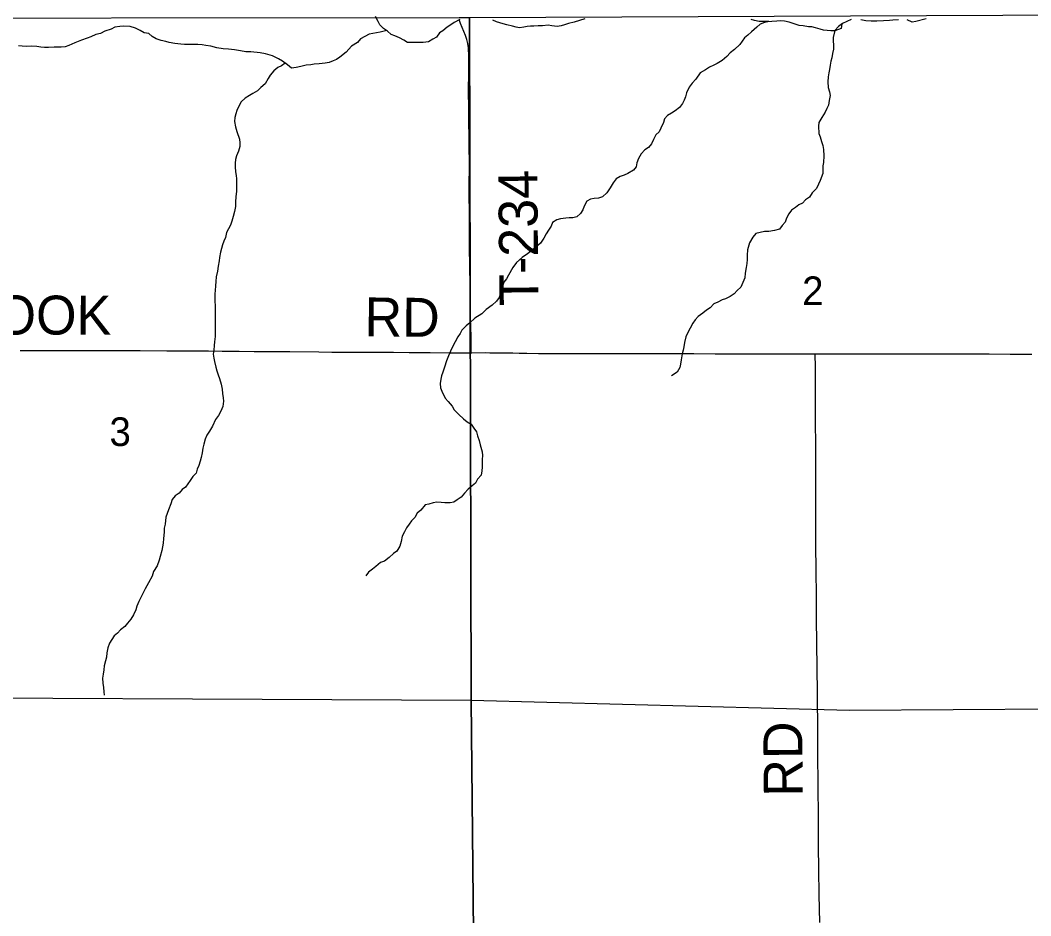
# Model space of a CAD drawing. Extents: x 0 to 34, y 0 to 22.
# Drawn here: x 2.961 to 4.435, y 14.561 to 15.868 of the extents above; entities that cross this region are included whole.
import ezdxf

# ---------------------------------------------------------------- set-up
doc = ezdxf.new("R2010")
doc.units = 0
for name, color, linetype in [('Default', 7, 'Continuous'), ('GM_X_County_Road', 7, 'Continuous'), ('GM_X_County_Road_Text', 7, 'Continuous'), ('GM_X_Minor_River', 7, 'Continuous'), ('GM_X_Section', 7, 'Continuous'), ('GM_X_Section_Text', 7, 'Continuous'), ('GM_X_Township_Road', 7, 'Continuous'), ('GM_X_Township_Road_Text', 7, 'Continuous')]:
    doc.layers.add(name, color=color, linetype=linetype)

msp = doc.modelspace()

# ---------------------------------------------------------------- linework, layer by layer
at = {"layer": 'Default'}
for points in [[(2.605, 14.1), (3.6266, 14.1), (3.6188, 14.8751), (2.6012, 14.88)], [(3.6266, 14.1), (4.6336, 14.1), (4.6247, 14.8633), (4.1707, 14.8603), (3.6188, 14.8751)]]:
    msp.add_lwpolyline(points, close=True, dxfattribs=at)
at = {"layer": 'GM_X_County_Road'}
for points in [[(2.9606, 15.3862), (2.9917, 15.3861), (3.0134, 15.3862), (3.0476, 15.3862), (3.0724, 15.3862), (3.1035, 15.3859), (3.1181, 15.386), (3.1359, 15.386), (3.1749, 15.3858), (3.1935, 15.3857), (3.2176, 15.3856), (3.2355, 15.3854), (3.2556, 15.3851), (3.268, 15.385), (3.2804, 15.3849), (3.3023, 15.3847), (3.3268, 15.3845), (3.3415, 15.3844), (3.3541, 15.3845), (3.3966, 15.3841), (3.4156, 15.3838), (3.4396, 15.3837), (3.4683, 15.3837), (3.4837, 15.3835), (3.5055, 15.3835), (3.5281, 15.3834), (3.559, 15.3831), (3.5869, 15.3826), (3.5962, 15.3828), (3.6077, 15.3826), (3.6186, 15.3827)], [(3.6186, 15.3827), (3.6197, 15.3828), (3.6397, 15.383), (3.6461, 15.3829), (3.6578, 15.3829), (3.6706, 15.3828), (3.6798, 15.3827), (3.6891, 15.3822), (3.6999, 15.3822), (3.717, 15.3819), (3.7418, 15.3818), (3.7574, 15.3818), (3.7729, 15.3819), (3.804, 15.3819), (3.8475, 15.3819), (3.8847, 15.3819), (3.9065, 15.3818), (3.9251, 15.3816), (3.9437, 15.3815), (3.9748, 15.3813), (4.009, 15.3813), (4.0338, 15.3813), (4.071, 15.3811), (4.0866, 15.3812), (4.1076, 15.3812), (4.1209, 15.3812)], [(4.1209, 15.3812), (4.151, 15.3814), (4.1728, 15.3812), (4.1976, 15.381), (4.2219, 15.3811), (4.2536, 15.3811), (4.3095, 15.3813), (4.3405, 15.3812), (4.3747, 15.3811), (4.4053, 15.3809), (4.4244, 15.3807), (4.4368, 15.3809)], [(4.1275, 14.551), (4.1269, 14.5913), (4.1262, 14.6284), (4.1258, 14.6626), (4.1255, 14.7029), (4.1251, 14.7526), (4.1247, 14.7961), (4.1246, 14.8272), (4.124, 14.8862), (4.123, 14.9949), (4.1228, 15.0291), (4.1225, 15.0632), (4.122, 15.1036), (4.122, 15.1253), (4.1217, 15.178), (4.1216, 15.2028), (4.1218, 15.2432), (4.1214, 15.2867), (4.1212, 15.3364), (4.1212, 15.3612), (4.1209, 15.3812)]]:
    msp.add_lwpolyline(points, dxfattribs=at)
at = {"layer": 'GM_X_Minor_River'}
for points in [[(3.6023, 15.8694), (3.5939, 15.8649), (3.589, 15.8618), (3.584, 15.858), (3.5776, 15.8527), (3.5726, 15.85), (3.568, 15.8436), (3.5627, 15.8405), (3.5566, 15.8367), (3.549, 15.836), (3.5436, 15.8356), (3.5318, 15.8356), (3.5261, 15.836), (3.5207, 15.839), (3.5142, 15.8425), (3.5074, 15.8455), (3.502, 15.8474), (3.4967, 15.8524), (3.4909, 15.8562), (3.4856, 15.8615), (3.4829, 15.8664), (3.4791, 15.8737)], [(3.7847, 15.8705), (3.7771, 15.8678), (3.7691, 15.8655), (3.7607, 15.8636), (3.755, 15.8617), (3.75, 15.8602), (3.7443, 15.8591), (3.7367, 15.8602), (3.7313, 15.861), (3.7229, 15.8602), (3.7165, 15.8602), (3.7104, 15.8598), (3.7054, 15.8595), (3.7004, 15.8591), (3.6955, 15.858), (3.6894, 15.8572), (3.6844, 15.858), (3.6791, 15.8595), (3.671, 15.8614), (3.6653, 15.8633), (3.6558, 15.866), (3.6504, 15.8686)], [(4.0531, 15.8662), (4.053, 15.8665), (4.0389, 15.8665), (4.0324, 15.868), (4.0275, 15.8696)], [(4.1736, 15.8695), (4.1668, 15.8664), (4.1607, 15.8638), (4.155, 15.8592), (4.1496, 15.8535), (4.147, 15.8433), (4.147, 15.8383), (4.1478, 15.8318), (4.1478, 15.8261), (4.1463, 15.8197), (4.1451, 15.8136), (4.1436, 15.8087), (4.1425, 15.8026), (4.1417, 15.7965), (4.1406, 15.7915), (4.1399, 15.7858), (4.1395, 15.7786), (4.1399, 15.7702), (4.1418, 15.7638), (4.1426, 15.7585), (4.1415, 15.7509), (4.1403, 15.7444)], [(4.2423, 15.8687), (4.2343, 15.8683), (4.2293, 15.8679), (4.2206, 15.8676), (4.2107, 15.8672), (4.2026, 15.8672), (4.195, 15.8676), (4.1874, 15.8687)], [(4.2828, 15.8702), (4.2679, 15.8664), (4.2622, 15.8656), (4.2553, 15.8687)], [(3.4956, 15.8531), (3.486, 15.8508), (3.4806, 15.8497), (3.47, 15.8482), (3.4635, 15.8448), (3.4574, 15.841), (3.4528, 15.836), (3.4444, 15.8307), (3.4364, 15.8216), (3.4273, 15.8144), (3.4223, 15.811), (3.4174, 15.8091), (3.4117, 15.8068), (3.4059, 15.8056), (3.3968, 15.8049), (3.3895, 15.8041), (3.3846, 15.803), (3.3781, 15.8026), (3.3701, 15.8007), (3.3632, 15.7992), (3.3567, 15.7984), (3.3506, 15.803), (3.3433, 15.8087), (3.3376, 15.8121), (3.3288, 15.8163), (3.3189, 15.8194), (3.3109, 15.8205), (3.2971, 15.8221), (3.2899, 15.8224), (3.2823, 15.8236), (3.2735, 15.8251), (3.2647, 15.8263), (3.2567, 15.8266), (3.2479, 15.8278), (3.2387, 15.8305), (3.2315, 15.8312), (3.2261, 15.8324), (3.22, 15.8331), (3.2006, 15.8331), (3.1952, 15.8335), (3.1864, 15.8343), (3.178, 15.8358), (3.1731, 15.8373), (3.1666, 15.8385), (3.1593, 15.8411), (3.1532, 15.8446), (3.1482, 15.8488), (3.1417, 15.8499), (3.1356, 15.8533), (3.1288, 15.8568), (3.1211, 15.8594), (3.1112, 15.8598), (3.1059, 15.859), (3.099, 15.8583), (3.0933, 15.8553), (3.0841, 15.8526), (3.078, 15.8488), (3.0711, 15.8473), (3.0639, 15.8442), (3.0582, 15.8423), (3.0502, 15.8393), (3.0403, 15.8351), (3.0319, 15.8313), (3.0262, 15.8294), (3.0204, 15.8291), (3.0105, 15.8291), (3.0021, 15.8287), (2.9964, 15.8287), (2.9907, 15.8291), (2.9849, 15.8298), (2.9777, 15.8306), (2.9704, 15.8302), (2.9636, 15.8306), (2.9582, 15.831)], [(4.1598, 15.8631), (4.1588, 15.8562), (4.1496, 15.8528), (4.1439, 15.8528), (4.1382, 15.8531), (4.1332, 15.8539), (4.1282, 15.8554), (4.1214, 15.8573), (4.116, 15.8585), (4.1111, 15.8589), (4.1034, 15.86), (4.0973, 15.8608), (4.0904, 15.8631), (4.0828, 15.8653), (4.0763, 15.8669), (4.0706, 15.8673), (4.0649, 15.8669), (4.0576, 15.8665), (4.0519, 15.8661), (4.0469, 15.865), (4.0405, 15.8627), (4.0355, 15.8581), (4.0279, 15.8513), (4.0226, 15.8467), (4.0176, 15.8426), (4.0111, 15.8331), (4.0031, 15.8258), (3.997, 15.8205), (3.9921, 15.8156), (3.9849, 15.8095), (3.978, 15.8053), (3.9731, 15.8027), (3.9666, 15.7996), (3.9609, 15.7958), (3.9532, 15.7913), (3.9468, 15.7821), (3.9414, 15.7764), (3.9369, 15.7704), (3.9331, 15.7624), (3.9316, 15.7567), (3.9297, 15.7517), (3.927, 15.7468), (3.9228, 15.7411), (3.9163, 15.7358), (3.9114, 15.7327), (3.9053, 15.7293), (3.9011, 15.7244), (3.8996, 15.719), (3.8958, 15.7107), (3.8931, 15.7054), (3.8882, 15.7012), (3.8848, 15.6943), (3.8821, 15.6879), (3.8775, 15.6826), (3.8722, 15.6791), (3.8669, 15.6734), (3.8631, 15.6666), (3.8604, 15.6601), (3.8597, 15.6544), (3.8555, 15.6495), (3.8475, 15.6445), (3.8422, 15.6423), (3.8361, 15.64), (3.8303, 15.6366), (3.8258, 15.6309), (3.8216, 15.6236), (3.8166, 15.6164), (3.8105, 15.6107), (3.8048, 15.6084), (3.7983, 15.6081), (3.793, 15.6069), (3.7877, 15.6039), (3.7839, 15.597), (3.782, 15.5913), (3.7786, 15.586), (3.7728, 15.5815), (3.7671, 15.5799), (3.7618, 15.5796), (3.7568, 15.5792), (3.7492, 15.5784), (3.7438, 15.5769), (3.7377, 15.5731), (3.7355, 15.5678), (3.7317, 15.5617), (3.7282, 15.5564), (3.7248, 15.5499), (3.7199, 15.5427), (3.7126, 15.5366), (3.7077, 15.5328), (3.7008, 15.5271), (3.6932, 15.5218), (3.6852, 15.5146), (3.6795, 15.5074), (3.6734, 15.496), (3.6704, 15.4906), (3.6666, 15.4857), (3.6647, 15.48), (3.6632, 15.4735), (3.6617, 15.4686), (3.6598, 15.4633), (3.656, 15.4583)], [(3.3478, 15.8052), (3.3472, 15.8057), (3.3418, 15.8019), (3.3369, 15.7992), (3.3308, 15.7943), (3.3255, 15.7882), (3.3228, 15.7833), (3.3182, 15.7757), (3.3118, 15.7699), (3.3068, 15.7654), (3.3003, 15.7612), (3.2954, 15.7582), (3.2889, 15.7544), (3.2832, 15.7494), (3.2794, 15.7418), (3.2767, 15.7365), (3.2752, 15.7316), (3.2737, 15.7262), (3.2733, 15.7205), (3.2749, 15.7126), (3.2768, 15.7061), (3.2806, 15.6947), (3.281, 15.6894), (3.2811, 15.684), (3.2792, 15.6772), (3.2765, 15.6703), (3.275, 15.665), (3.2742, 15.6597), (3.2743, 15.6544), (3.275, 15.6471), (3.2758, 15.6418), (3.2762, 15.6369), (3.2766, 15.6316), (3.2766, 15.6258), (3.2762, 15.6186), (3.2755, 15.6103), (3.2751, 15.603), (3.2748, 15.5962), (3.2733, 15.589), (3.2714, 15.5817), (3.2695, 15.5749), (3.2676, 15.5692), (3.2645, 15.5639), (3.2619, 15.5582), (3.2604, 15.5513), (3.2577, 15.5456), (3.2558, 15.5403), (3.2547, 15.535), (3.2532, 15.5297), (3.2517, 15.5221), (3.2509, 15.5171), (3.2498, 15.5091), (3.2487, 15.5019), (3.2468, 15.4935), (3.246, 15.4867), (3.2457, 15.4806), (3.2453, 15.4738), (3.2449, 15.4688), (3.2449, 15.4624), (3.2446, 15.4574), (3.245, 15.4517), (3.245, 15.4369), (3.2454, 15.4319), (3.2454, 15.4148), (3.2451, 15.4065), (3.2443, 15.3989), (3.244, 15.3932), (3.2432, 15.3867), (3.2425, 15.3806), (3.2432, 15.3749), (3.2444, 15.37), (3.2463, 15.3616), (3.2479, 15.3566), (3.2498, 15.3506), (3.2517, 15.3452), (3.254, 15.3369), (3.2552, 15.3296), (3.256, 15.3232), (3.2571, 15.3171), (3.2575, 15.3122), (3.2564, 15.3045), (3.2533, 15.2973), (3.2499, 15.2912), (3.2457, 15.2852), (3.2412, 15.2757), (3.237, 15.2684), (3.2332, 15.2623), (3.2305, 15.2566), (3.2287, 15.2494), (3.2271, 15.2437), (3.2264, 15.2365), (3.2249, 15.23), (3.2234, 15.2243), (3.2215, 15.2182), (3.2192, 15.2129), (3.2173, 15.2072), (3.2127, 15.2019), (3.2086, 15.1962), (3.2021, 15.1867), (3.1971, 15.1829), (3.1926, 15.178)], [(4.1403, 15.7444), (4.1377, 15.7394), (4.1354, 15.7341), (4.1305, 15.7265), (4.1263, 15.7189), (4.1255, 15.7136), (4.1263, 15.7029), (4.1279, 15.698), (4.1302, 15.6912), (4.1321, 15.6855), (4.1329, 15.6794), (4.1333, 15.6702), (4.1329, 15.6607), (4.1322, 15.6558), (4.1322, 15.6505), (4.1318, 15.6444), (4.128, 15.6341), (4.1257, 15.6288), (4.1227, 15.6227), (4.1166, 15.6163), (4.1124, 15.6098), (4.1067, 15.606), (4.1025, 15.6011), (4.0972, 15.5988), (4.0922, 15.595), (4.0865, 15.5912), (4.0823, 15.5855), (4.0789, 15.5794), (4.077, 15.5737), (4.0728, 15.5684), (4.0686, 15.5634), (4.0614, 15.5611), (4.0534, 15.56), (4.0469, 15.56), (4.0404, 15.5585), (4.0343, 15.557), (4.0301, 15.5517), (4.0252, 15.5433), (4.0222, 15.533), (4.0218, 15.5254), (4.0214, 15.519), (4.0211, 15.5133), (4.0203, 15.5072), (4.0188, 15.4988), (4.0181, 15.4923), (4.0154, 15.4855), (4.0124, 15.4787), (4.007, 15.4737), (4.0025, 15.4688), (3.9967, 15.465), (3.9899, 15.4616), (3.9849, 15.46), (3.9788, 15.4566), (3.9731, 15.454), (3.9674, 15.4486), (3.9621, 15.4452), (3.9567, 15.4407), (3.9503, 15.4357), (3.9457, 15.4308), (3.9423, 15.4258), (3.9385, 15.4186), (3.9343, 15.4114), (3.932, 15.4061), (3.9301, 15.3977), (3.929, 15.3916), (3.9282, 15.3867), (3.9267, 15.3814), (3.9252, 15.3726), (3.9241, 15.3662), (3.9233, 15.3612), (3.9192, 15.3544), (3.9112, 15.349)], [(3.656, 15.4583), (3.6495, 15.4522), (3.6407, 15.4458), (3.6346, 15.4397), (3.624, 15.4332), (3.6171, 15.4264), (3.6114, 15.4222), (3.6053, 15.4158), (3.603, 15.4108), (3.5992, 15.4059), (3.5916, 15.3914), (3.5886, 15.385), (3.5856, 15.3781), (3.5829, 15.3709), (3.5799, 15.3618), (3.5776, 15.3546), (3.5757, 15.3492), (3.5746, 15.3443), (3.5734, 15.3378), (3.5742, 15.3317), (3.5761, 15.3268), (3.5811, 15.3165), (3.5853, 15.3116), (3.5911, 15.3047), (3.5941, 15.2994), (3.601, 15.2926), (3.6075, 15.2865), (3.6129, 15.2819), (3.6186, 15.2785), (3.6228, 15.2728), (3.6267, 15.2671), (3.6282, 15.2617), (3.6305, 15.2549), (3.632, 15.2484), (3.6347, 15.2382), (3.6355, 15.2328), (3.6351, 15.2271), (3.6348, 15.2211), (3.6348, 15.2157), (3.6344, 15.2104), (3.6333, 15.2043), (3.6283, 15.1982), (3.6253, 15.1922), (3.6204, 15.1887), (3.6143, 15.1838), (3.6089, 15.1777), (3.6044, 15.172), (3.5986, 15.1678), (3.5933, 15.1648), (3.5884, 15.1637), (3.5803, 15.1637), (3.575, 15.1641), (3.5685, 15.1644), (3.5635, 15.1637), (3.5571, 15.1618), (3.5517, 15.1606), (3.5453, 15.153), (3.5399, 15.1485), (3.5365, 15.1424), (3.5319, 15.1375), (3.5285, 15.1325), (3.5243, 15.1272), (3.5213, 15.1215), (3.5182, 15.115), (3.5167, 15.1074), (3.5145, 15.1006), (3.5103, 15.093), (3.5053, 15.0896), (3.4992, 15.0839), (3.4924, 15.0785), (3.4867, 15.0763), (3.4798, 15.0709), (3.4749, 15.0668), (3.4688, 15.0626), (3.4653, 15.0569)], [(3.1926, 15.178), (3.1869, 15.1738), (3.1827, 15.1685), (3.1804, 15.162), (3.177, 15.1536), (3.1751, 15.1479), (3.1732, 15.1426), (3.1724, 15.1327), (3.1709, 15.1266), (3.1706, 15.1206), (3.1698, 15.1114), (3.1691, 15.1046), (3.1672, 15.0943), (3.1649, 15.0852), (3.1634, 15.0799), (3.1604, 15.0715), (3.1551, 15.0635), (3.1532, 15.0567), (3.1478, 15.0468), (3.1433, 15.0381), (3.1395, 15.0312), (3.1361, 15.0244), (3.1338, 15.0194), (3.1311, 15.013), (3.1296, 15.0076), (3.1262, 15), (3.122, 14.994), (3.1171, 14.9879), (3.1133, 14.9829), (3.1072, 14.9784), (3.1026, 14.9734), (3.0976, 14.9696), (3.0942, 14.9639), (3.0912, 14.9586), (3.0885, 14.9521), (3.087, 14.9445), (3.0867, 14.9385), (3.0851, 14.9328), (3.0833, 14.9255), (3.0829, 14.9198), (3.0818, 14.9134), (3.081, 14.9077), (3.0814, 14.9004), (3.0822, 14.894), (3.0826, 14.8875), (3.083, 14.8826)]]:
    msp.add_lwpolyline(points, dxfattribs=at)
at = {"layer": 'GM_X_Section'}
for points in [[(3.6011, 15.8725), (3.6166, 15.8725), (3.6188, 14.8751), (2.6012, 14.88), (2.5857, 15.8713)], [(3.6166, 15.8725), (4.6171, 15.8766), (4.6247, 14.8633), (4.1707, 14.8603), (3.6188, 14.8751)]]:
    msp.add_lwpolyline(points, close=True, dxfattribs=at)
at = {"layer": 'GM_X_Township_Road'}
msp.add_lwpolyline([(3.6186, 15.3827), (3.6186, 15.3847), (3.6187, 15.3978), (3.6186, 15.407), (3.6183, 15.4194), (3.618, 15.4349), (3.6179, 15.4473), (3.6176, 15.4627), (3.6174, 15.4813), (3.617, 15.5092), (3.6166, 15.5371), (3.6165, 15.5557), (3.6164, 15.5805), (3.616, 15.6207), (3.6162, 15.661), (3.616, 15.6827), (3.6153, 15.7353), (3.6151, 15.7693), (3.6153, 15.7879), (3.6156, 15.8034), (3.6155, 15.8158), (3.6147, 15.8282), (3.6139, 15.8343), (3.6125, 15.8403), (3.6105, 15.8462), (3.6033, 15.8634), (3.6013, 15.8696)], dxfattribs=at)

# ---------------------------------------------------------------- texts
at = {"layer": 'GM_X_County_Road_Text'}
for s, rotation, p in [('MILLBROOK', 359.885, (2.6502, 15.4101)), ('RD', 359.5091, (3.463, 15.4068)), ('RD', 90.4991, (4.1028, 14.7349))]:
    msp.add_text(s, height=0.05682, rotation=rotation, dxfattribs=at).set_placement(p)
at = {"layer": 'GM_X_Section_Text'}
for s, p in [('2', (4.1018, 15.4523)), ('3', (3.091, 15.2466))]:
    msp.add_text(s, height=0.0419, rotation=0, dxfattribs=at).set_placement(p)
at = {"layer": 'GM_X_Township_Road_Text'}
msp.add_text('T-234', height=0.05682, rotation=90.5573, dxfattribs=at).set_placement((3.7171, 15.4515))

doc.saveas('drawing.dxf')
